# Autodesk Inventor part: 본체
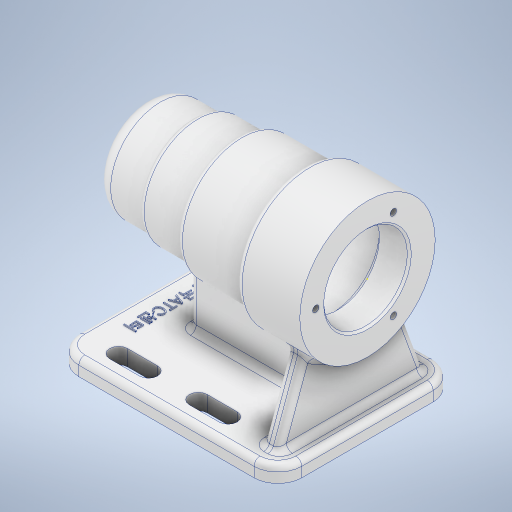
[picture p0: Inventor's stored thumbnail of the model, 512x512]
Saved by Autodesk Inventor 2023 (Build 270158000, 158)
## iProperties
Created: 2022-07
Part Number: 본체
Material: 알루미늄 6061
Document SubType Name: Modeling
Designer: owner
Density: 2.7 g/cm^3
Appearance: 알루미늄 - 평지
Mass: 695.707 g
Surface Area: 710.79 cm^2
Volume: 257.669 cm^3
Author: owner
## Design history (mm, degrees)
sketch "스케치1"
  geometry: L1 (0, 0)-(0, 34); L2 (0, 34)-(-32, 34); L3 (-32, 34)-(-32, 30); L4 (-32, 30)-(-66, 30); L5 (-66, 30)-(-66, 27); L6 (-66, 27)-(-88, 27); L7 (-88, 27)-(-88, 25); L8 (-88, 25)-(-104, 25); L9 (-112, 17)-(-112, 0); L10 (-112, 0)-(0, 0); L11 (0, 21)-(-15, 21); L12 (-15, 21)-(-15, 21); L13 (-18, 24)-(-66, 24); L14 (-69, 21)-(-69, 21); L15 (-69, 21)-(-80.7, 21); L16 (-81, 20.7)-(-81, 17.5); L17 (-81, 17.5)-(-98.7, 17.5); L18 (-99, 17.2)-(-99, 16); L19 (-99, 16)-(-102.7, 16); L20 (-103, 15.7)-(-103, 10.5); L21 (-103, 10.5)-(-103, 10.5); L22 (-106, 7.5)-(-106, 0); A1 r 8 centre (-104, 17) between (-104, 25) and (-112, 17); A2 r 0.3 centre (-102.7, 15.7) between (-102.7, 16) and (-103, 15.7); A3 r 0.3 centre (-98.7, 17.2) between (-98.7, 17.5) and (-99, 17.2); A4 r 0.3 centre (-80.7, 20.7) between (-80.7, 21) and (-81, 20.7); A5 r 3 centre (-66, 21) between (-66, 24) and (-69, 21); A6 r 3 centre (-18, 21) between (-15, 21) and (-18, 24); A7 r 3 centre (-103, 7.5) between (-103, 10.5) and (-106, 7.5); 4 further points
  constraints: 44 end point, 19 perpendicular, 14 point on circle, 14 tangent, 7 centre point, 4 equal radius, 4 point on line, 2 vertical, 1 horizontal
  dimensions: "d0" = 34 distance of L1.start L1.end; "d1" = 25 distance between parallel lines of L10 L8; "d2" = 112 distance between parallel lines of L1 L9; "d3" = 24 distance between parallel lines of L7 L9; "d4" = 22 distance between parallel lines of L5 L7; "d5" = 34 distance between parallel lines of L3 L5; "d6" = 27 distance between parallel lines of L10 L6; "d7" = 30 distance between parallel lines of L10 L4; "d8" = 21 distance between parallel lines of L10 L11; "d9" = 15 distance between parallel lines of L1 L12; "d10" = 54 distance between parallel lines of L14 L12; "d11" = 24 distance between parallel lines of L10 L13; "d12" = 12 distance between parallel lines of L16 L14; "d13" = 21 distance between parallel lines of L10 L15; "d14" = 18 distance between parallel lines of L18 L16; "d15" = 17.5 distance between parallel lines of L10 L17; "d16" = 10.5 distance between parallel lines of L10 L21; "d17" = 4 distance of L18.end point (-103, 16); "d18" = 16 distance between parallel lines of L10 L19; "d19" = 3 distance between parallel lines of L22 L20; "d20" = 8 radius of A1; "d21" = 0.3 radius of A2; "d22" = 3 radius of A5
revolve "회전1" sketch "스케치1" stored, may be unused: angle "d23" = 90 deg
node "작업 평면1"
sketch "스케치2"
  geometry: L1 (0, 0)-(0, -45); L2 (0, -45)-(112, -45); L3 (112, -45)-(112, 0); L4 (112, 0)-(0, 0); L5 (0, 45)-(112, 45); L6 (112, 45)-(112, 0); L7 (0, 0)-(0, 45)
  constraints: 14 end point, 2 perpendicular, 2 symmetric about line, 2 vertical
  dimensions: "d27" = 45 distance between parallel lines of L4 L2; "d28" = 112 distance between parallel lines of L1 L3
extrude "돌출1" join sketch "스케치2" distance "d29" = 8; taper "d30" = 0 deg
fillet "모깎기1" dims "d31" = 12
sketch "스케치4"
  geometry: 1 further point
sketch "스케치5"
  geometry: L1 (-92, -33)-(-77, -33); L2 (-92, -37.5)-(-77, -37.5); L3 (-77, -28.5)-(-92, -28.5); L4 (-112, 33)-(-112, -33) reference; L5 (-100, -45)-(-12, -45) reference; L6 (-52, -33)-(-37, -33); L7 (-52, -37.5)-(-37, -37.5); L8 (-37, -28.5)-(-52, -28.5); L9 (-92, 33)-(-77, 33); L10 (-92, 28.5)-(-77, 28.5); L11 (-77, 37.5)-(-92, 37.5); L12 (-12, 45)-(-100, 45) reference; L13 (-52, 33)-(-37, 33); L14 (-52, 28.5)-(-37, 28.5); L15 (-37, 37.5)-(-52, 37.5); A1 r 4.5 centre (-92, -33) between (-92, -28.5) and (-92, -37.5); A2 r 4.5 centre (-77, -33) between (-77, -37.5) and (-77, -28.5); A3 r 4.5 centre (-52, -33) between (-52, -28.5) and (-52, -37.5); A4 r 4.5 centre (-37, -33) between (-37, -37.5) and (-37, -28.5); A5 r 4.5 centre (-92, 33) between (-92, 37.5) and (-92, 28.5); A6 r 4.5 centre (-77, 33) between (-77, 28.5) and (-77, 37.5); A7 r 4.5 centre (-52, 33) between (-52, 37.5) and (-52, 28.5); A8 r 4.5 centre (-37, 33) between (-37, 28.5) and (-37, 37.5); 5 further points
  constraints: 32 end point, 16 point on circle, 16 tangent, 8 centre point, 4 horizontal, 4 midpoint, 4 parallel
  dimensions: "d38" = 9 diameter of A2; "d39" = 20 distance from line of L1.start L4; "d40" = 12 distance from line of L5 point (-84.5, -33); "d41" = 15 distance of L1.end L1.start; "d42" = 7.5 distance of point (-44.5, -33) L6.end; "d43" = 9 diameter of A4; "d44" = 25 distance of L6.start L1.end; "d45" = 12 distance from line of L5 L6.end; "d46" = 7.5 distance of point (-84.5, 33) L9.end; "d47" = 9 diameter of A6; "d48" = 20 distance from line of L4 L9.start; "d49" = 12 distance from line of point (-84.5, 33) L12; "d50" = 7.5 distance of point (-44.5, 33) L13.end; "d51" = 9 diameter of A8; "d52" = 25 distance of L13.start L9.end; "d53" = 12 distance between parallel lines of L12 L13
extrude "돌출2" cut sketch "스케치5" distance "d54" = 10; taper "d55" = 0 deg
node "작업 평면2"
sketch "스케치8"
  geometry: L1 (-62, 45)-(-62, 33) reference; L2 (-62, 37)-(-24.658, 23.409); L3 (-62, 45)-(-70, 45) reference; L4 (-24.658, -23.409)-(-62, -37); L5 (-62, -33)-(-62, -45) reference; L6 (-70, -45)-(-62, -45) reference; L7 (-62, -28.5)-(-62, -37.5) reference; L8 (-62, 37)-(-62, -37.5); A1 r 34 centre (0, 0) between (-24.658, 23.409) and (-24.658, -23.409) reference; 5 further points
  constraints: 6 end point, 2 point on line, 1 point on circle, 2 other
  dimensions: "d57" = 8 distance from line of L3 L2.start; "d58" = 110 deg angle of L1 L2; "d59" = 8 distance from line of L6 L4.end; "d60" = 110 deg angle of L5 L4
extrude "돌출3" join sketch "스케치8" distance "d61" = 8; taper "d62" = 0 deg
node "작업 평면3"
node "작업 평면4"
sketch "스케치11"
  geometry: L1 (16, -4)-(85, -4); L2 (85, -4)-(85, 4); L3 (85, 4)-(16, 4); L4 (16, 4)-(16, -4); 2 further points
  constraints: 8 end point, 3 perpendicular, 1 horizontal, 1 horizontal alignment, 1 midpoint
  dimensions: "d70" = 16 distance from line of L4 point (0, 0); "d71" = 8 distance between parallel lines of L3 L1; "d72" = 69 distance between parallel lines of L2 L4
extrude "돌출4" join sketch "스케치11" stored distance "d73" = 8; taper "d74" = 0 deg
fillet "모깎기2" dims "d75" = 3
fillet "모깎기3" dims "d76" = 3
fillet "모깎기4" dims "d77" = 3
sketch "스케치12" dims "d85" = 52
  geometry: 3 further points
  constraints: 2 horizontal alignment, 1 coincident, 2 other
hole "구멍1" sketch "스케치12" at (-26, 0) diameter "d78" = 3.242; stored, may be unused: countersink angle "d82" = 90 deg, drill point angle "d84" = 118 deg; dims "d79" = 8, "d80" = 4, "d81" = 2, "d83" = 11
sketch "스케치14"
  geometry: L1 (-112, 33)-(-112, -33) reference; 3 further points
  constraints: 1 horizontal alignment, 1 midpoint, 1 other
  dimensions: "d89" = 12 distance from line of L1 point (-100, 0)
feature "엠보싱1" sketch "스케치14" dims "d0" = 34, "d1" = 25, "d2" = 112, "d3" = 24, "d4" = 22, "d5" = 34, "d6" = 27, "d7" = 30, "d8" = 21, "d9" = 15, "d10" = 54, "d11" = 24, "d12" = 12, "d13" = 21, "d14" = 18, "d15" = 17.5, "d16" = 10.5, "d17" = 4, "d18" = 16, "d19" = 3, "d20" = 8, "d21" = 0.3, "d22" = 3, "d90" = 0.5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
fillet "모깎기5" dims "d92" = 3
chamfer "모따기1" distance "d93" = 1; stored, may be unused: second distance "d94" = 2, angle "d95" = 45 deg
node "솔리드1"
pattern_circular "원형 패턴1" dims angle "d87" = 360 deg
feature "A9D066F2-1C7D-4E18-AEED-F7BC21143FA4" dims "d78" = 3.242, "d79" = 8, "d80" = 4, "d81" = 2, "d82" = 90 deg, "d83" = 11, "d84" = 118 deg
other parameters: "d56" = -8, "d63" = 62, "d64" = -62
